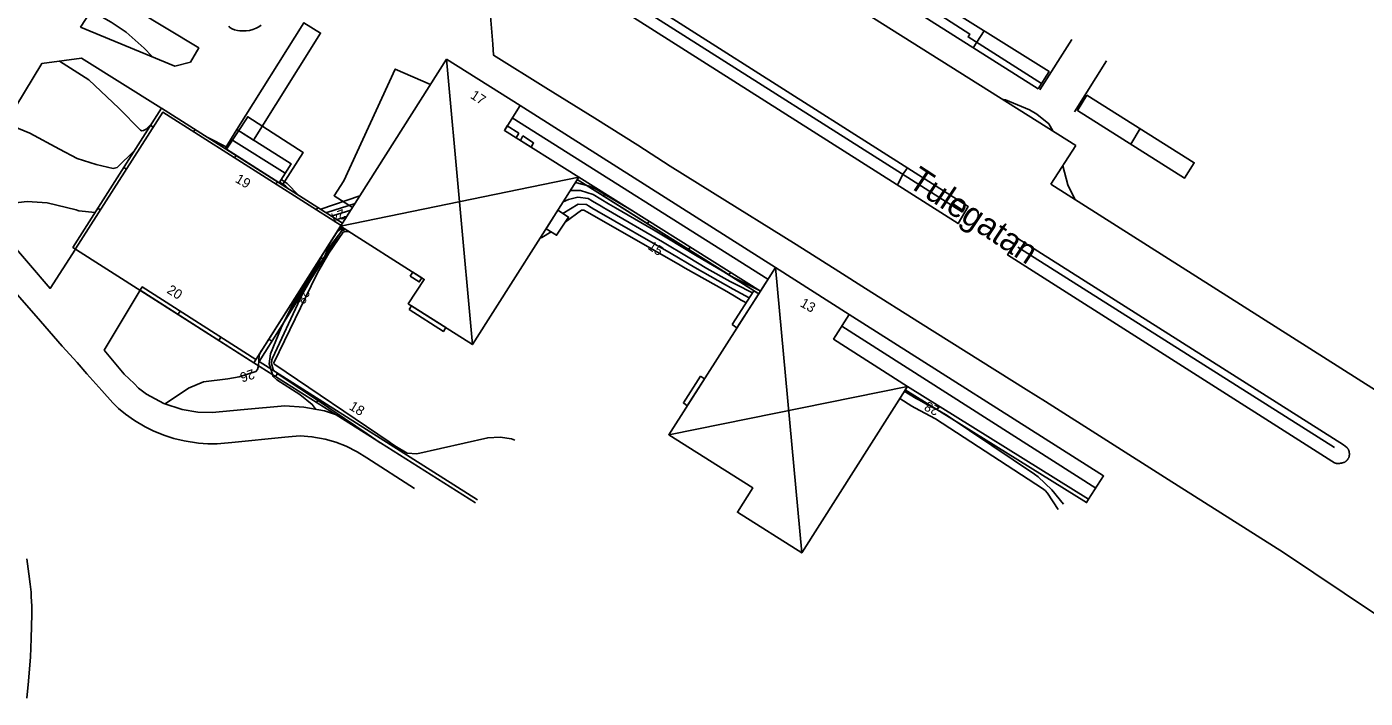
# Model space of a CAD drawing. Extents: x 67169 to 69652, y 20189 to 22818.
# Drawn here: x 69428.4 to 69565.9, y 21050.5 to 21119.5 of the extents above; entities that cross this region are included whole.
import ezdxf

# ---------------------------------------------------------------- set-up
doc = ezdxf.new("R2010")
doc.units = 0
for name, color, linetype in [('BYGGNAD_HUSLIV', 7, 'Continuous'), ('BYGGNAD_HUSLIV 11', 7, 'Continuous'), ('BYGGNAD_HUSLIV 13', 7, 'Continuous'), ('BYGGNADSDETALJER', 7, 'Continuous'), ('BYGGNADSDETALJER 19', 7, 'Continuous'), ('BYGGNADSSYMBOLER', 7, 'Continuous'), ('BYGGNADSSYMBOLER 30', 7, 'Continuous'), ('GATUNAMN', 7, 'Continuous'), ('HOJDKURVOR_2014', 7, 'Continuous'), ('HOJDKURVOR_2014 5M', 7, 'Continuous'), ('HOJDKURVOR_TEXTER_2014', 7, 'Continuous'), ('Instruktioner', 7, 'Continuous'), ('MUR_STAKET', 7, 'Continuous'), ('MUR_STAKET_SYMBOL', 7, 'Continuous'), ('Std_Ritningsstämpel', 7, 'Continuous'), ('VAGAR 121', 7, 'Continuous'), ('VAGAR 123', 7, 'Continuous')]:
    doc.layers.add(name, color=color, linetype=linetype)

msp = doc.modelspace()

# ---------------------------------------------------------------- linework, layer by layer
at = {"layer": 'BYGGNAD_HUSLIV'}
for points in [[(69471.48, 21116.21), (69479.04, 21111.44), (69477.42, 21108.88), (69485.06, 21104.07), (69474.13, 21086.87), (69467.55, 21091.06), (69469.18, 21093.57), (69460.57, 21099.03), (69460.8, 21099.36), (69471.48, 21116.21)], [(69442.2, 21111.18), (69460.79, 21099.36), (69460.57, 21099.03), (69451.67, 21085), (69433.1, 21096.86), (69442.2, 21111.18)], [(69479.04, 21111.44), (69505.27, 21094.78), (69503.72, 21092.37), (69485.06, 21104.07), (69477.42, 21108.88), (69479.04, 21111.44)], [(69448.87, 21106.94), (69454.61, 21103.28), (69456.74, 21106.62), (69451.05, 21110.29), (69448.87, 21106.94)], [(69505.27, 21094.78), (69512.83, 21089.95), (69511.23, 21087.43), (69518.82, 21082.58), (69507.96, 21065.46), (69501.36, 21069.65), (69502.94, 21072.15), (69494.3, 21077.61), (69505.27, 21094.78)], [(69511.24, 21087.44), (69518.82, 21082.58), (69537.44, 21070.98), (69538.97, 21073.37), (69512.83, 21089.95), (69511.24, 21087.43)]]:
    msp.add_lwpolyline(points, dxfattribs=at)
at = {"layer": 'BYGGNAD_HUSLIV 11'}
for points in [[(69471.48, 21116.21), (69479.04, 21111.44), (69477.42, 21108.88), (69485.06, 21104.07), (69474.13, 21086.87), (69467.55, 21091.06), (69469.18, 21093.57), (69460.57, 21099.03), (69460.8, 21099.36), (69471.48, 21116.21)], [(69505.27, 21094.78), (69512.83, 21089.95), (69511.23, 21087.43), (69518.82, 21082.58), (69507.96, 21065.46), (69501.36, 21069.65), (69502.94, 21072.15), (69494.3, 21077.61), (69505.27, 21094.78)]]:
    msp.add_lwpolyline(points, dxfattribs=at)
at = {"layer": 'BYGGNAD_HUSLIV 13'}
msp.add_lwpolyline([(69442.2, 21111.18), (69460.79, 21099.36), (69460.57, 21099.03), (69451.67, 21085), (69433.1, 21096.86), (69442.2, 21111.18)], dxfattribs=at)
at = {"layer": 'BYGGNADSDETALJER'}
for points in [[(69532.25, 21113.15), (69518.93, 21121.57), (69520.07, 21123.3), (69533.37, 21114.93), (69532.25, 21113.15)], [(69520.33, 21121.92), (69525.23, 21118.78), (69525.05, 21118.48), (69532.6, 21113.7)], [(69537.26, 21112.5), (69548.28, 21105.56), (69547.27, 21103.97), (69536.29, 21110.93), (69537.26, 21112.5)], [(69478.9, 21108.58), (69478.62, 21108.13), (69477.42, 21108.88), (69477.72, 21109.35), (69478.9, 21108.58)], [(69479.33, 21108.31), (69480.42, 21107.6), (69480.16, 21107.16), (69479.06, 21107.85), (69479.33, 21108.31)], [(69482.92, 21100.68), (69484.01, 21099.97), (69482.79, 21098.1), (69481.71, 21098.77), (69482.92, 21100.68)], [(69467.75, 21093.91), (69468, 21094.31), (69468.93, 21093.72), (69468.68, 21093.31), (69467.75, 21093.91)], [(69500.83, 21088.92), (69503.04, 21092.41), (69503.55, 21092.09), (69501.31, 21088.59), (69500.83, 21088.92)], [(69467.63, 21090.47), (69467.88, 21090.85), (69471.39, 21088.61), (69471.15, 21088.23), (69467.63, 21090.47)], [(69497.56, 21083.61), (69497.97, 21083.35), (69496.21, 21080.59), (69495.81, 21080.87), (69497.56, 21083.61)]]:
    msp.add_lwpolyline(points, dxfattribs=at)
at = {"layer": 'BYGGNADSDETALJER 19'}
for points in [[(69532.25, 21113.15), (69518.93, 21121.57), (69520.07, 21123.3), (69533.37, 21114.93), (69532.25, 21113.15)], [(69520.33, 21121.92), (69525.23, 21118.78), (69525.05, 21118.48), (69532.6, 21113.7)], [(69537.26, 21112.5), (69548.28, 21105.56), (69547.27, 21103.97), (69536.29, 21110.93), (69537.26, 21112.5)]]:
    msp.add_lwpolyline(points, dxfattribs=at)
at = {"layer": 'BYGGNADSSYMBOLER'}
for p, q in [((69526.72, 21119.12), (69525.59, 21117.36)), ((69526.72, 21119.12), (69526.72, 21119.12)), ((69471.48, 21116.21), (69474.13, 21086.87)), ((69478.23, 21110.16), (69504.49, 21093.58)), ((69542.73, 21109.06), (69541.77, 21107.45)), ((69542.73, 21109.06), (69542.73, 21109.06)), ((69449.33, 21107.99), (69454.9, 21104.48)), ((69460.57, 21099.03), (69485.06, 21104.07)), ((69505.27, 21094.78), (69507.96, 21065.46)), ((69512.07, 21088.76), (69538.16, 21072.13)), ((69494.3, 21077.61), (69518.82, 21082.58))]:
    msp.add_line(p, q, dxfattribs=at)
at = {"layer": 'BYGGNADSSYMBOLER 30'}
for p, q in [((69471.48, 21116.21), (69474.13, 21086.87)), ((69460.57, 21099.03), (69485.06, 21104.07)), ((69505.27, 21094.78), (69507.96, 21065.46)), ((69494.3, 21077.61), (69518.82, 21082.58))]:
    msp.add_line(p, q, dxfattribs=at)
at = {"layer": 'HOJDKURVOR_2014'}
for p, q in [((69447.04, 21108.1), (69448.83, 21107.2)), ((69460.75, 21099.29), (69460.75, 21099.29)), ((69482.3, 21099.73), (69482.32, 21099.73))]:
    msp.add_line(p, q, dxfattribs=at)
for points in [[(69434.8, 21121.33), (69436.48, 21120.32), (69437.01, 21120), (69438.56, 21118.97), (69440.41, 21117.34), (69441.19, 21116.5)], [(69431.71, 21115.99), (69434.74, 21114.06), (69437.83, 21111.15), (69440.04, 21108.9), (69440.18, 21108.85), (69440.33, 21108.86), (69440.63, 21109.02), (69441.15, 21109.52)], [(69533.78, 21108.79), (69533.77, 21108.83), (69533.34, 21109.54), (69532.12, 21110.54), (69531.37, 21110.98), (69528.91, 21112.02), (69528.53, 21112.1)], [(69426.17, 21109.6), (69426.35, 21109.55), (69428.68, 21108.6), (69431.73, 21106.95), (69433.53, 21106), (69435.47, 21105.36), (69437.23, 21104.97), (69437.64, 21105.08), (69439.43, 21106.82)], [(69518.84, 21105.02), (69518.39, 21104.43), (69517.8, 21103.27)], [(69536.02, 21101.81), (69535.31, 21103.27), (69534.77, 21105.25)], [(69454.32, 21103.56), (69454.63, 21103.38), (69454.92, 21103.18), (69455.39, 21102.79)], [(69454.49, 21103.83), (69455.11, 21103.43), (69456.27, 21102.23)], [(69424.03, 21100.64), (69425.77, 21101.27), (69428.4, 21101.58), (69430.44, 21101.43), (69433.42, 21100.72), (69433.6, 21100.65), (69433.69, 21100.63), (69435.38, 21100.45)], [(69458.54, 21100.79), (69458.54, 21100.79), (69458.56, 21100.8), (69462.56, 21102.14)], [(69459.12, 21100.42), (69459.18, 21100.45), (69462.08, 21101.38)], [(69483.45, 21101.54), (69484, 21101.79), (69484.98, 21102.02), (69486.02, 21101.87), (69486.46, 21101.61), (69487.36, 21101.08), (69487.62, 21100.92), (69487.88, 21100.77), (69493.66, 21097.43), (69496.31, 21095.86), (69498.22, 21094.7), (69500.62, 21093.35), (69501.23, 21093.03), (69502.9, 21092.18)], [(69484.19, 21102.7), (69485.24, 21102.7), (69486.55, 21102.29), (69488.11, 21101.35), (69488.84, 21100.92), (69492.74, 21098.65), (69494.12, 21097.84), (69497.22, 21095.95), (69500.95, 21093.77), (69501.29, 21093.6), (69503.57, 21092.47)], [(69459.7, 21100.05), (69459.76, 21100.09), (69461.64, 21100.68)], [(69483.42, 21100.35), (69485.01, 21101.31), (69485.8, 21101.28), (69485.85, 21101.26), (69486.07, 21101.13), (69486.61, 21100.8), (69486.76, 21100.71), (69486.92, 21100.62), (69494.56, 21096.23), (69496.98, 21094.8), (69500.93, 21092.58), (69502.58, 21091.68)], [(69483.68, 21099.46), (69485.33, 21100.69), (69485.59, 21100.69), (69485.96, 21100.47), (69495.47, 21095.04), (69495.66, 21094.92), (69496, 21094.73), (69500.02, 21092.45), (69501.04, 21091.88), (69501.76, 21091.45), (69502, 21091.31), (69502.24, 21091.15)], [(69464.67, 21076.79), (69463.34, 21077.69), (69461, 21079.29), (69458.64, 21080.87), (69454.17, 21083.84), (69454.01, 21083.96), (69453.68, 21084.32), (69453.5, 21084.93), (69453.53, 21085.3), (69453.59, 21085.49), (69456.43, 21091.57), (69456.69, 21092.1), (69457.57, 21093.63), (69459.02, 21096.03), (69459.26, 21096.64), (69460.71, 21098.55), (69461.1, 21098.69)], [(69460.21, 21098.46), (69460.76, 21098.87), (69460.79, 21098.89)], [(69478.48, 21077.04), (69478.16, 21077.2), (69476.97, 21077.37), (69475.71, 21077.29), (69468.41, 21075.64), (69467.44, 21075.71), (69466.16, 21076.48), (69465.73, 21076.77), (69465.59, 21076.87), (69453.83, 21084.83), (69453.78, 21084.87), (69453.75, 21084.98), (69458.11, 21094.03), (69458.14, 21094.09), (69458.23, 21094.26), (69459.4, 21096.25), (69460.85, 21098.41), (69460.98, 21098.46), (69461.17, 21098.5), (69461.24, 21098.49), (69461.44, 21098.47)], [(69481.08, 21097.8), (69481.25, 21097.87), (69482.23, 21098.45)], [(69458.02, 21080.21), (69457.98, 21080.32), (69457.68, 21080.72), (69456.41, 21081.73), (69454.03, 21083.25), (69453.67, 21083.6), (69453.25, 21084.88), (69453.38, 21085.93), (69454.5, 21088.59), (69455.54, 21090.76), (69458.22, 21094.95), (69458.73, 21096.13)], [(69457.37, 21093.97), (69458, 21094.87), (69458.07, 21094.99), (69458.15, 21095.13), (69458.21, 21095.3)], [(69442.57, 21080.77), (69444.97, 21082.38), (69446.52, 21083.04), (69449.01, 21083.34), (69450.17, 21083.55), (69451.89, 21084.11), (69452.06, 21084.3), (69452.17, 21084.7), (69452.24, 21085.77), (69452.45, 21086.23)], [(69518.03, 21081.33), (69519.27, 21080.56), (69519.57, 21080.38), (69521.72, 21079.25), (69532.71, 21072.07), (69532.96, 21071.88), (69533.21, 21071.62), (69534.3, 21069.93)], [(69518.5, 21082.09), (69519.73, 21081.34), (69519.99, 21081.18), (69520.79, 21080.75), (69521.9, 21080.18), (69522.74, 21079.7), (69523.01, 21079.52), (69531.89, 21073.55), (69532.26, 21073.27), (69533.64, 21071.93), (69534.85, 21070.46)]]:
    msp.add_lwpolyline(points, dxfattribs=at)
at = {"layer": 'HOJDKURVOR_2014 5M'}
msp.add_line((69439.19, 21092.98), (69439.19, 21092.98), dxfattribs=at)
for points in [[(69484.72, 21103.53), (69486.17, 21103.15), (69486.85, 21102.83), (69487.92, 21102.18), (69490.64, 21100.57)], [(69460.24, 21099.71), (69460.33, 21099.75), (69461.22, 21100.03)]]:
    msp.add_lwpolyline(points, dxfattribs=at)
at = {"layer": 'MUR_STAKET'}
for p, q in [((69524.49, 21100.47), (69434.03, 21157.91)), ((69535.71, 21118.22), (69532.42, 21113.04)), ((69535.7, 21118.22), (69532.42, 21113.04)), ((69539.28, 21116.03), (69535.99, 21110.78)), ((69539.28, 21116.03), (69535.99, 21110.78)), ((69441.08, 21109.41), (69441.35, 21109.22)), ((69445.67, 21108.97), (69445.5, 21108.72)), ((69449.88, 21106.29), (69449.71, 21106.05)), ((69438.32, 21105.08), (69438.59, 21104.89)), ((69454.1, 21103.61), (69453.94, 21103.36)), ((69487.76, 21102.37), (69487.61, 21102.14)), ((69435.66, 21100.88), (69435.91, 21100.71)), ((69458.26, 21100.97), (69458.09, 21100.72)), ((69460.64, 21099.1), (69451.67, 21085)), ((69492.28, 21099.54), (69492.12, 21099.3)), ((69496.51, 21096.89), (69496.34, 21096.64)), ((69530.16, 21096.87), (69562.69, 21076.31)), ((69458.55, 21095.81), (69458.84, 21095.63)), ((69500.66, 21094.29), (69500.49, 21094.03)), ((69455.91, 21091.67), (69456.22, 21091.48)), ((69444.12, 21090.31), (69443.89, 21089.97)), ((69448.3, 21087.64), (69448.07, 21087.3)), ((69453.22, 21087.43), (69453.54, 21087.22)), ((69451.67, 21085), (69474.46, 21070.62)), ((69454.13, 21083.93), (69453.91, 21083.59)), ((69518.59, 21082.22), (69537.22, 21070.63)), ((69458.35, 21081.26), (69458.13, 21080.92)), ((69522.07, 21080.56), (69521.84, 21080.21))]:
    msp.add_line(p, q, dxfattribs=at)
for points in [[(69449.93, 21108.96), (69456.83, 21119.95), (69458.53, 21118.88), (69451.63, 21107.89), (69449.93, 21108.96)], [(69469.82, 21113.61), (69466.2, 21115.18), (69460.91, 21103.71), (69459.93, 21102.17), (69461.81, 21100.95)], [(69433.1, 21096.86), (69442.2, 21111.18), (69460.79, 21099.36)], [(69433.35, 21096.7), (69442.33, 21110.74), (69460.64, 21099.1)], [(69433.35, 21096.7), (69442.33, 21110.74), (69460.64, 21099.1)], [(69485.06, 21104.07), (69503.72, 21092.37), (69503.55, 21092.1), (69484.91, 21103.84), (69485.06, 21104.07)], [(69484.91, 21103.84), (69499.57, 21094.61), (69503.55, 21092.1)], [(69460.86, 21098.84), (69452.22, 21085.14), (69474.65, 21070.93)], [(69451.9, 21085.35), (69440.22, 21092.79), (69440, 21092.46), (69451.67, 21085)], [(69537.44, 21070.98), (69537.22, 21070.63), (69518.59, 21082.22), (69518.82, 21082.58), (69537.44, 21070.98)]]:
    msp.add_lwpolyline(points, dxfattribs=at)
at = {"layer": 'MUR_STAKET_SYMBOL'}
for p, q in [((69456.53, 21119.43), (69456.53, 21119.43)), ((69457.68, 21119.42), (69457.68, 21119.42)), ((69456.03, 21118.68), (69456.03, 21118.68)), ((69535.7, 21118.22), (69535.7, 21118.22)), ((69454.88, 21116.84), (69454.88, 21116.84)), ((69455.36, 21117.6), (69455.36, 21117.6)), ((69457.05, 21116.52), (69457.05, 21116.52)), ((69457.86, 21117.81), (69457.86, 21117.81)), ((69534.94, 21117.02), (69534.94, 21117.02)), ((69454.19, 21115.74), (69454.19, 21115.74)), ((69456.37, 21115.44), (69456.37, 21115.44)), ((69501.28, 21115.2), (69501.28, 21115.2)), ((69534.15, 21115.77), (69534.15, 21115.77)), ((69534.21, 21115.86), (69534.21, 21115.86)), ((69539.28, 21116.03), (69539.28, 21116.03)), ((69453.45, 21114.57), (69453.45, 21114.57)), ((69455.46, 21113.99), (69455.46, 21113.99)), ((69538.39, 21114.6), (69538.39, 21114.6)), ((69538.48, 21114.74), (69538.48, 21114.74)), ((69452.74, 21113.45), (69452.74, 21113.45)), ((69454.64, 21112.69), (69454.64, 21112.69)), ((69537.66, 21113.44), (69537.66, 21113.44)), ((69451.27, 21111.1), (69451.27, 21111.1)), ((69452, 21112.25), (69452, 21112.25)), ((69453.81, 21111.36), (69453.81, 21111.36)), ((69450.55, 21109.94), (69450.55, 21109.94)), ((69453.06, 21110.17), (69453.06, 21110.17)), ((69450.72, 21108.46), (69450.72, 21108.46)), ((69452.2, 21108.8), (69452.2, 21108.8)), ((69451.82, 21104.7), (69451.82, 21104.7)), ((69438.01, 21103.99), (69438.01, 21103.99)), ((69522.11, 21101.98), (69522.11, 21101.98)), ((69493.68, 21098.32), (69493.68, 21098.32)), ((69535.51, 21093.48), (69535.51, 21093.48)), ((69550.11, 21084.26), (69550.11, 21084.26))]:
    msp.add_line(p, q, dxfattribs=at)
at = {"layer": 'Std_Ritningsstämpel'}
for points in [[(69471.48, 21116.21), (69460.8, 21099.36), (69460.57, 21099.03), (69469.18, 21093.57), (69467.55, 21091.06), (69474.13, 21086.87), (69485.06, 21104.07), (69477.42, 21108.88), (69479.04, 21111.44)], [(69442.2, 21111.18), (69433.1, 21096.86), (69451.67, 21085), (69460.57, 21099.03), (69460.79, 21099.36)], [(69479.04, 21111.44), (69477.42, 21108.88), (69485.06, 21104.07), (69503.72, 21092.37), (69505.27, 21094.78)], [(69448.72, 21107.03), (69454.28, 21103.5), (69455.51, 21105.46), (69449.93, 21108.96)], [(69505.27, 21094.78), (69494.3, 21077.61), (69502.94, 21072.15), (69501.36, 21069.65), (69507.96, 21065.46), (69518.82, 21082.58), (69511.23, 21087.43), (69512.83, 21089.95)], [(69511.24, 21087.44), (69518.82, 21082.58), (69537.44, 21070.98), (69538.97, 21073.37), (69512.83, 21089.95)]]:
    msp.add_lwpolyline(points, close=True, dxfattribs=at)
at = {"layer": 'VAGAR 121'}
for p, q in [((69536.11, 21107.33), (69533.56, 21103.36)), ((69436.32, 21086.29), (69440, 21092.46))]:
    msp.add_line(p, q, dxfattribs=at)
for points in [[(69536.11, 21107.33), (69451.79, 21160.47)], [(69425.99, 21145.11), (69428.38, 21144.99), (69429.33, 21144.88), (69431.34, 21144.67), (69432.75, 21144.42), (69434.2, 21144.01), (69434.89, 21143.78), (69436, 21143.35), (69437.34, 21142.73), (69438.46, 21142.19), (69439.02, 21141.88), (69445.64, 21138.45), (69446.89, 21137.8), (69448.56, 21136.94), (69455.04, 21133.6), (69459.12, 21131.46), (69464.26, 21128.77), (69475.85, 21122.27), (69476.22, 21117.73)], [(69477.62, 21131.25), (69525.07, 21101.06), (69524.03, 21099.31), (69477.93, 21128.61)], [(69433.87, 21119.48), (69436.31, 21123.26), (69446.02, 21117.36), (69445.17, 21115.88), (69443.55, 21115.49), (69433.87, 21119.48)], [(69449.12, 21119.59), (69449.22, 21119.44), (69449.44, 21119.33), (69449.7, 21119.23), (69449.99, 21119.16), (69450.26, 21119.11), (69450.88, 21119.11), (69451.22, 21119.15), (69451.58, 21119.25), (69451.91, 21119.39), (69452.19, 21119.53), (69452.45, 21119.71)], [(69566.8, 21059.25), (69557.46, 21065.49), (69545.59, 21073.02), (69533.01, 21081.01), (69531.03, 21082.25), (69520.18, 21089.06), (69514.52, 21092.63), (69511.77, 21094.38), (69507.39, 21097.16), (69498.79, 21102.49), (69494.44, 21105.21), (69491.14, 21107.35), (69486.71, 21110.14), (69481.68, 21113.24), (69476.31, 21116.6), (69476.22, 21117.73)], [(69442.14, 21111.21), (69433.97, 21116.3), (69429.89, 21115.75), (69423.75, 21105.6), (69424.05, 21100.44), (69430.75, 21092.65), (69433.37, 21096.69)], [(69570.08, 21080.18), (69533.56, 21103.37)], [(69562.42, 21074.9), (69529.11, 21096.09), (69530.15, 21097.76), (69563.63, 21076.57), (69563.96, 21076.31), (69563.97, 21076.3), (69563.98, 21076.29), (69563.99, 21076.28), (69564.01, 21076.26), (69564.03, 21076.24), (69564.04, 21076.22), (69564.06, 21076.19), (69564.08, 21076.16), (69564.1, 21076.13), (69564.12, 21076.09), (69564.13, 21076.06), (69564.14, 21076.03), (69564.15, 21076.01), (69564.16, 21075.99), (69564.17, 21075.96), (69564.18, 21075.94), (69564.19, 21075.9), (69564.19, 21075.86), (69564.21, 21075.8), (69564.21, 21075.74), (69564.22, 21075.69), (69564.22, 21075.64), (69564.22, 21075.6), (69564.22, 21075.54), (69564.21, 21075.48), (69564.21, 21075.45), (69564.2, 21075.39), (69564.19, 21075.33), (69564.18, 21075.31), (69564.17, 21075.29), (69564.16, 21075.27), (69564.16, 21075.25), (69564.15, 21075.23), (69564.14, 21075.21), (69564.13, 21075.19), (69564.11, 21075.17), (69564.1, 21075.15), (69564.08, 21075.12), (69564.06, 21075.09), (69564.05, 21075.07), (69564.02, 21075.03), (69563.99, 21075), (69563.97, 21074.98), (69563.94, 21074.95), (69563.91, 21074.92), (69563.89, 21074.9), (69563.86, 21074.88), (69563.84, 21074.86), (69563.82, 21074.85), (69563.81, 21074.84), (69563.78, 21074.82), (69563.75, 21074.8), (69563.73, 21074.79), (69563.71, 21074.78), (69563.68, 21074.77), (69563.64, 21074.76), (69563.6, 21074.75), (69563.54, 21074.73), (69563.49, 21074.72), (69563.42, 21074.7), (69563.35, 21074.69), (69563.28, 21074.67), (69563.23, 21074.66), (69563.19, 21074.66), (69563.16, 21074.65), (69563.11, 21074.65), (69563.07, 21074.65), (69563.02, 21074.65), (69562.98, 21074.65), (69562.94, 21074.65), (69562.91, 21074.66), (69562.88, 21074.66), (69562.86, 21074.67), (69562.82, 21074.68), (69562.79, 21074.69), (69562.77, 21074.7), (69562.73, 21074.71), (69562.7, 21074.73), (69562.42, 21074.9)], [(69468.17, 21072.08), (69463.28, 21075.23), (69462.3, 21075.85), (69461.18, 21076.42), (69460.1, 21076.85), (69459, 21077.16), (69457.65, 21077.4), (69456.44, 21077.48), (69455.62, 21077.44), (69454.87, 21077.35), (69449.43, 21076.82), (69447.93, 21076.69), (69446.97, 21076.69), (69445.98, 21076.73), (69444.54, 21076.97), (69443.48, 21077.22), (69442.44, 21077.57), (69441.33, 21078), (69440.53, 21078.42), (69439.42, 21079.07), (69438.51, 21079.72), (69437.79, 21080.32), (69437.19, 21080.89), (69436.06, 21082.17), (69434.51, 21083.88), (69433.52, 21085.03), (69432, 21086.72), (69429.76, 21089.28), (69426.44, 21093.07)], [(69428.35, 21050.53), (69428.55, 21052.28), (69428.6, 21053.15), (69428.74, 21054.74), (69428.82, 21056.67), (69428.86, 21059.16), (69428.86, 21059.99), (69428.82, 21060.99), (69428.8, 21061.42), (69428.7, 21062.24), (69428.58, 21063.3), (69428.35, 21064.87)]]:
    msp.add_lwpolyline(points, dxfattribs=at)
at = {"layer": 'VAGAR 123'}
msp.add_lwpolyline([(69460.16, 21079.64), (69458.93, 21080.05), (69456.82, 21080.43), (69454.87, 21080.57), (69450.68, 21080.19), (69447.39, 21079.9), (69445.94, 21079.92), (69444.32, 21080.2), (69442.43, 21080.81), (69440.67, 21081.78), (69439.85, 21082.39), (69439.38, 21082.88), (69438.37, 21083.82), (69436.32, 21086.29)], dxfattribs=at)

# ---------------------------------------------------------------- texts
at = {"layer": 'GATUNAMN'}
msp.add_text('Tulegatan', height=2.5, rotation=326.5493, dxfattribs=at).set_placement((69518.75, 21103.22))
at = {"layer": 'HOJDKURVOR_TEXTER_2014'}
for s, rotation, p in [('24', 202.381, (69460.84, 21100.83)), ('28', 244.2531, (69456.61, 21092.7)), ('26', 197.7069, (69451.58, 21084.37)), ('28', 152.5384, (69522.22, 21080.39))]:
    msp.add_text(s, height=1, rotation=rotation, dxfattribs=at).set_placement(p)
at = {"layer": 'Instruktioner'}
for s, rotation, p in [('17', 326.9693, (69473.85, 21112.26)), ('19', 329.7787, (69449.69, 21103.62)), ('15', 326.6996, (69492.07, 21096.75)), ('20', 327.9201, (69442.67, 21092.24)), ('13', 330.2995, (69507.72, 21090.85)), ('18', 328.6759, (69461.39, 21080.27))]:
    msp.add_text(s, height=1, rotation=rotation, dxfattribs=at).set_placement(p)

doc.saveas('drawing.dxf')
